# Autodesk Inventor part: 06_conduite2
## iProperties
Created: 2002-11
Part Number: 06_conduite2
Material: Par défaut
Document SubType Name: Modélisation
Designer: FIEVET
Control State: 0
Master: False
Checked Out: False
Shininess: 60.0
Length Units: 11269
Angle Units: 11279
Time Units: 11290
Mass Units: 11283
Length Display Precision: 3
Angle Display Precision: 2
Compacted: True
Density: 1.0
Volumn: 0.20356059077290878
Area: 8.160074662571244
PropertySet Name: Model Information
Author: FIEVET
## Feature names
1. Hélicoïde1
